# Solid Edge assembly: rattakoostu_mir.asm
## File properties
Author: Türk
Template: Iso Assembly.asm
Last saved by: Türk
Revision: 2
Application: Solid Edge
Username: Türk
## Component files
VlegR18_2_mir.par
Rehv.par
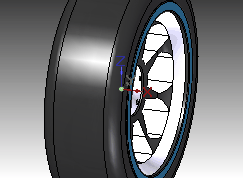
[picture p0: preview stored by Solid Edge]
